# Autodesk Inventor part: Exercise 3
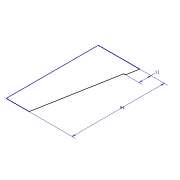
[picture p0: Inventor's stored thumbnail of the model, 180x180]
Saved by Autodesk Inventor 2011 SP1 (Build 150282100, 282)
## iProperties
Created: 2010-11
Part Number: Exercise 3
Document SubType Name: Modeling
Designer: SERGIO
Density: 1 g/cm^3
Author: SERGIO
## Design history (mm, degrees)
sketch "Sketch1"
  geometry: L1 (0, 0)-(20.9, 0); L2 (20.9, 0)-(34.173, 73); L3 (34.173, 73)-(35.75, 73); L4 (35.75, 73)-(37.75, 84); L5 (37.75, 84)-(0, 84); L6 (0, 0)-(0, 84)
  constraints: 12 end point, 2 horizontal, 2 parallel, 1 perpendicular
  dimensions: "Height" = 84 distance from line of L1 L4.end; "d3" = 11 distance from line of L3 L4.end
body "Solid1"
